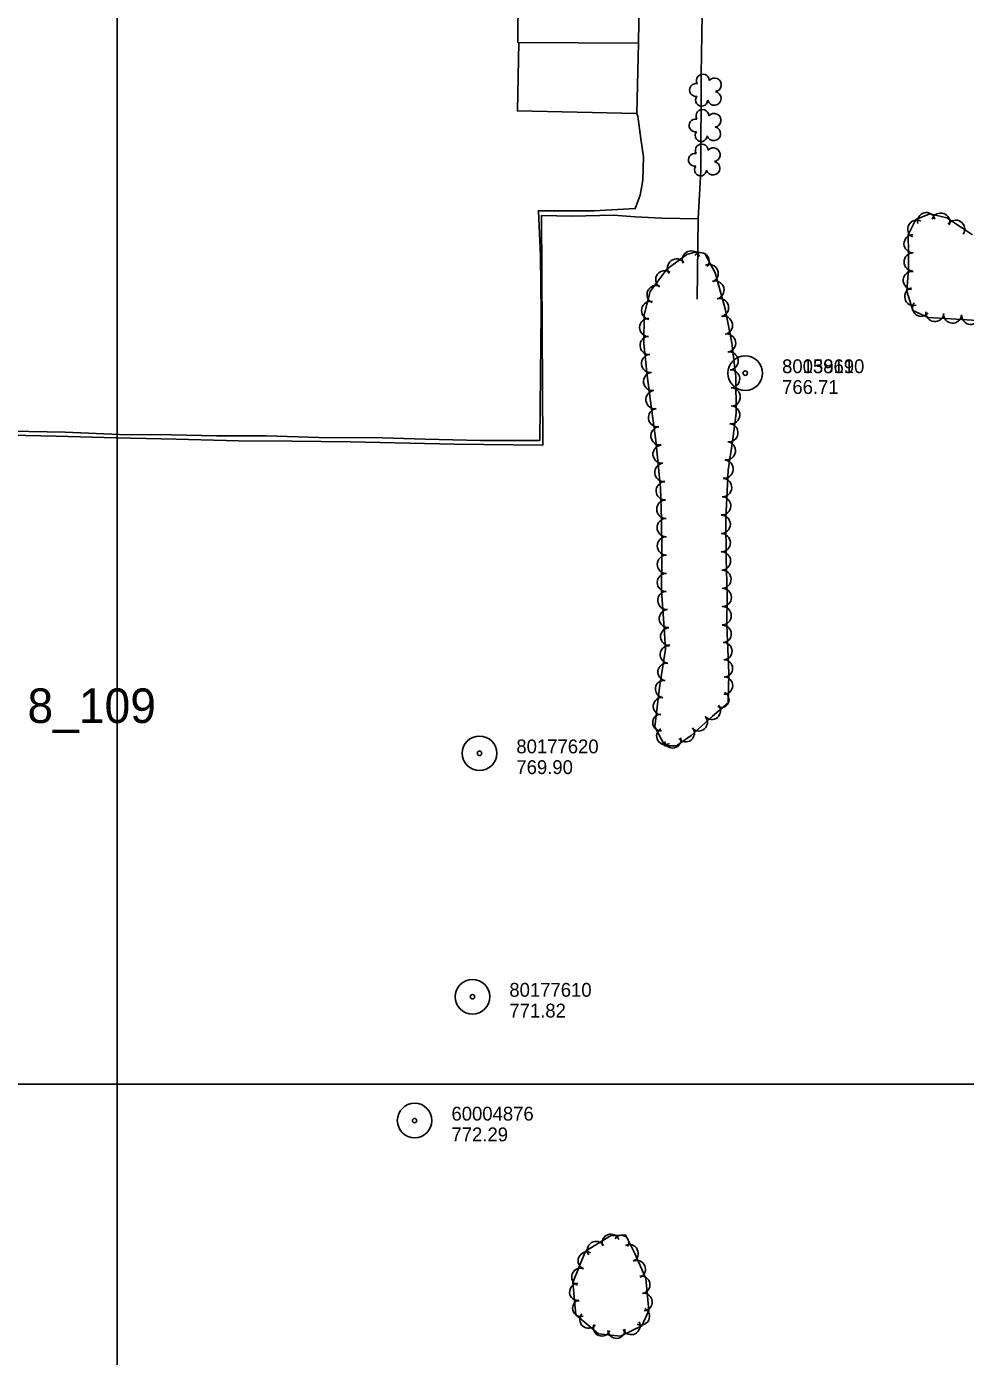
# Model space of a CAD drawing. Extents: x 591954 to 597000, y 198576 to 213500.
# Drawn here: x 594461 to 594868, y 203882 to 204459 of the extents above; entities that cross this region are included whole.
import ezdxf

# ---------------------------------------------------------------- set-up
doc = ezdxf.new("R2010")
doc.units = 0
for name, color, linetype in [('Level 10', 7, 'Continuous'), ('Level 12', 7, 'Continuous'), ('Level 15', 7, 'Continuous'), ('Level 17', 7, 'Continuous'), ('Level 18', 7, 'Continuous'), ('Level 4', 7, 'Continuous'), ('Level 6', 7, 'Continuous')]:
    doc.layers.add(name, color=color, linetype=linetype)

msp = doc.modelspace()

# ---------------------------------------------------------------- linework, layer by layer
at = {"layer": 'Level 10'}
for p, q in [((594500, 204000), (594500, 205500)), ((594500, 203000), (594500, 204500)), ((593000, 204000), (595500, 204000)), ((593500, 204000), (595500, 204000))]:
    msp.add_line(p, q, dxfattribs=at)
at = {"layer": 'Level 12'}
msp.add_lwpolyline([(594674.68, 204574.47), (594673.92, 204451.9), (594726.25, 204451.57), (594728.14, 204573.62), (594674.68, 204574.47)], dxfattribs=at)
at = {"layer": 'Level 15'}
for points in [[(594754.08, 204472.87), (594753.51, 204438.08), (594753.28, 204396.43), (594752.17, 204375.34)], [(594752.17, 204375.34), (594736.43, 204375.71), (594724.75, 204376.29), (594715.46, 204377), (594697.51, 204376.56), (594684.17, 204376.79), (594684.8, 204277.26), (594646.2, 204277.59), (594601.26, 204278.64), (594576, 204279.01), (594552.68, 204279.16), (594525.61, 204279.87), (594499.47, 204280.41), (594473.45, 204281.09), (594446.78, 204281.74), (594435.38, 204281.84), (594425.62, 204279.31), (594415.91, 204281.81)], [(594752.17, 204375.34), (594751.77, 204340.63)]]:
    msp.add_lwpolyline(points, dxfattribs=at)
at = {"layer": 'Level 17'}
for points in [[(594725.58, 204421.13), (594673.67, 204422.2), (594674.28, 204451.9)], [(594726.21, 204451.57), (594725.58, 204421.13)], [(594725.58, 204421.13), (594725.93, 204419.94), (594727.25, 204410.16), (594728.39, 204402.27), (594728.18, 204392.16), (594726.96, 204385.66), (594724.87, 204379.87), (594706.82, 204378.94), (594682.82, 204378.9), (594683.75, 204359.27), (594683.97, 204334.47), (594683.77, 204307.86), (594683.38, 204279.19), (594657.72, 204279.26), (594633.71, 204279.8), (594615.08, 204280.37), (594587.5, 204280.59), (594564.63, 204281.21), (594543.07, 204281.25), (594523.57, 204281.66), (594500.96, 204281.92), (594477.34, 204282.87), (594453.76, 204283.23)]]:
    msp.add_lwpolyline(points, dxfattribs=at)
at = {"layer": 'Level 18'}
for points in [[(594871.24, 204368.51), (594866.87, 204371.41), (594860.14, 204375.87), (594852.65, 204377.58), (594846.61, 204375.17), (594843.33, 204368.53), (594843.42, 204360.93), (594843.46, 204353.69), (594842.67, 204344.08), (594845.29, 204335.65), (594851.92, 204332.57), (594862.02, 204332.06), (594875.71, 204331.1)], [(594764.6, 204199.17), (594764.77, 204212.46), (594764.29, 204228.02), (594764.17, 204245.43), (594765.23, 204266.33), (594767.08, 204278.8), (594768.64, 204291.15), (594768.45, 204306.94), (594766.72, 204321.68), (594763.82, 204336.38), (594759.51, 204351.95), (594755.03, 204360.39), (594751.29, 204361.06), (594747.27, 204359.89), (594738.5, 204353.62), (594731.39, 204343.89), (594728.69, 204333.74), (594728.56, 204321.28), (594729.95, 204307.46), (594731.71, 204294.15), (594733.82, 204279.3), (594735.84, 204258.75), (594736.18, 204245.1), (594736.35, 204230.87), (594736.21, 204214.02), (594737.41, 204197.95)], [(594737.41, 204197.95), (594737.92, 204188.71), (594735.44, 204172.05), (594733.33, 204155.01), (594737.68, 204146.84), (594742.73, 204146.74), (594749.05, 204151.28), (594758.35, 204159.72), (594765.18, 204165.45), (594765.47, 204178.29), (594764.6, 204199.17)], [(594730.72, 203901.8), (594729.38, 203915.75), (594724.71, 203926.56), (594720.55, 203934.66), (594714.04, 203934.2), (594703.29, 203927.56), (594697.82, 203913.93), (594699.08, 203899.94), (594708.95, 203891.7), (594718.38, 203890.77), (594727.77, 203895.21), (594730.72, 203901.8)]]:
    msp.add_lwpolyline(points, dxfattribs=at)
for centre, radius, start, end in [((594754.21, 204435.37), 2.78, 1.39455, 209.16754), ((594759.25, 204433.52), 2.97, 278.42366, 139.65754), ((594751.21, 204431.3), 2.78, 78.07156, 279.08261), ((594759.14, 204427.66), 2.97, 196.07448, 79.04774), ((594753.67, 204426.9), 2.61, 140.77971, 358.71232), ((594751, 204415.93), 2.78, 78.07156, 279.08261), ((594754, 204420.01), 2.78, 1.39455, 209.16754), ((594759.04, 204418.15), 2.97, 278.42366, 139.65754), ((594753.46, 204411.53), 2.61, 140.77971, 358.71232), ((594758.93, 204412.29), 2.97, 196.07448, 79.04774), ((594753.7, 204405.09), 2.78, 1.39455, 209.16754), ((594758.74, 204403.24), 2.97, 278.42366, 139.65754), ((594750.7, 204401.02), 2.78, 78.07156, 279.08261), ((594758.63, 204397.38), 2.97, 196.07448, 79.04774), ((594753.16, 204396.62), 2.61, 140.77971, 358.71232), ((594851.19, 204374.32), 3.81, 14.08767, 194.07234), ((594857.46, 204374.05), 3.89, 341.97598, 161.96066), ((594846.96, 204370.95), 3.88, 61.74191, 241.72659), ((594863.93, 204370.89), 3.94, 326.4448, 146.42948), ((594845.44, 204364.58), 3.94, 90.6411, 270.62578), ((594749.1, 204357.64), 3.86, 21.67135, 201.65603), ((594753.36, 204357.15), 3.59, 318.02994, 138.01462), ((594845.46, 204356.69), 3.93, 89.76001, 269.74469), ((594742.79, 204354.08), 3.96, 36.09353, 216.07821), ((594756.92, 204351.71), 3.94, 292.96781, 112.95248), ((594737.7, 204349), 3.97, 53.84544, 233.83012), ((594759.41, 204344.51), 3.97, 285.46607, 105.45074), ((594845.11, 204348.67), 3.93, 85.29119, 265.27586), ((594733.86, 204342.62), 3.9, 64.71425, 244.69893), ((594845.72, 204341.67), 3.91, 104.95797, 284.94265), ((594731.53, 204335.67), 3.95, 77.76138, 257.74606), ((594761.41, 204336.89), 3.96, 283.91069, 103.89537), ((594848.89, 204336.81), 3.7, 144.6896, 324.67428), ((594730.71, 204328.26), 3.97, 89.42266, 269.40734), ((594763.11, 204329.24), 3.97, 281.19864, 101.18332), ((594854.89, 204334.69), 3.9, 173.70726, 353.69194), ((594862.59, 204334.05), 3.93, 176.49582, 356.4805), ((594870.46, 204333.53), 3.94, 175.97081, 355.95548), ((594764.49, 204321.52), 3.96, 279.04341, 99.02809), ((594730.89, 204320.48), 3.96, 93.32869, 273.31336), ((594731.52, 204312.67), 3.97, 95.75131, 275.73599), ((594765.56, 204313.74), 3.97, 276.6732, 96.65788), ((594732.41, 204304.84), 3.97, 97.27779, 277.26247), ((594766.22, 204305.98), 3.96, 273.06757, 93.05225), ((594733.43, 204296.99), 3.97, 97.6128, 277.59748), ((594766.48, 204298.14), 3.97, 270.72265, 90.70733), ((594734.52, 204289.15), 3.97, 98.1153, 278.09998), ((594766.25, 204290.4), 3.96, 265.84264, 85.82732), ((594735.59, 204281.26), 3.97, 97.40233, 277.387), ((594765.47, 204282.63), 3.97, 262.75186, 82.73654), ((594736.5, 204273.31), 3.97, 95.61334, 275.59802), ((594764.39, 204274.81), 3.97, 261.57937, 81.56405), ((594737.27, 204265.42), 3.97, 95.60545, 275.59013), ((594763.39, 204266.86), 3.96, 264.0978, 84.08248), ((594762.77, 204258.85), 3.97, 267.08142, 87.0661), ((594737.85, 204257.41), 3.97, 92.76903, 272.75371), ((594738.15, 204249.43), 3.97, 91.43037, 271.41505), ((594762.37, 204250.92), 3.97, 267.08179, 87.06647), ((594738.3, 204241.47), 3.97, 90.73709, 270.72177), ((594762.15, 204242.9), 3.97, 269.81985, 89.80453), ((594762.17, 204234.94), 3.97, 270.4265, 90.41118), ((594738.38, 204233.53), 3.97, 90.51316, 270.49783), ((594738.38, 204225.56), 3.97, 89.52383, 269.50851), ((594762.28, 204226.98), 3.97, 271.26432, 91.249), ((594738.33, 204217.64), 3.97, 89.73321, 269.71789), ((594762.49, 204219.03), 3.97, 271.75539, 91.74007), ((594738.6, 204209.88), 3.97, 94.28673, 274.27141), ((594762.62, 204211.16), 3.97, 270.10156, 90.08624), ((594739.17, 204202.01), 3.92, 94.28425, 274.26893), ((594762.57, 204203.25), 3.97, 269.26388, 89.24856), ((594762.8, 204195.37), 3.73, 272.41537, 92.40005), ((594739.59, 204194.21), 3.77, 93.14953, 273.13421), ((594739.39, 204186.4), 3.76, 84.03819, 264.02287), ((594763.1, 204187.88), 3.77, 272.41861, 92.40329), ((594738.45, 204178.85), 3.77, 81.55284, 261.53751), ((594763.36, 204180.38), 3.77, 271.62034, 91.60502), ((594763.38, 204172.95), 3.77, 268.70744, 88.69211), ((594737.39, 204171.42), 3.77, 82.31955, 262.30423), ((594762.14, 204166.85), 3.43, 243.80089, 63.78557), ((594736.43, 204163.96), 3.77, 82.95714, 262.94182), ((594758.09, 204162.01), 3.77, 220.73433, 40.719), ((594736.05, 204156.91), 3.63, 92.22573, 272.21041), ((594752.41, 204156.99), 3.77, 222.22151, 42.20619), ((594737.81, 204150.99), 3.69, 120.18024, 300.16492), ((594746.77, 204152.24), 3.76, 217.90401, 37.88869), ((594741.1, 204149.44), 3.59, 192.37624, 12.36092), ((594714.24, 203931.25), 3.73, 21.01594, 201.00062), ((594718.83, 203931.28), 3.21, 327.71054, 147.69522), ((594703.87, 203923.42), 3.81, 66.87919, 246.86387), ((594707.85, 203928.01), 3.84, 31.72087, 211.70554), ((594722.3, 203926.66), 3.83, 295.8675, 115.85217), ((594725.46, 203919.77), 3.84, 293.34063, 113.32531), ((594701.07, 203916.43), 3.82, 69.43053, 249.4152), ((594727.43, 203912.98), 3.81, 278.75382, 98.7385), ((594700.2, 203909.92), 3.84, 95.14596, 275.13064), ((594701.3, 203902.87), 3.64, 104.48115, 284.46583), ((594728.35, 203905.51), 3.84, 275.51386, 95.49853), ((594704.59, 203897.95), 3.84, 140.15905, 320.14373), ((594727.32, 203899.28), 3.75, 244.06091, 64.04559), ((594710.36, 203894.41), 3.67, 158.73288, 338.71756), ((594716.67, 203893.48), 3.72, 183.71666, 3.70134), ((594723.12, 203895.23), 3.84, 205.29308, 25.27776)]:
    msp.add_arc(centre, radius, start, end, dxfattribs=at)
at = {"layer": 'Level 6'}
for centre, radius in [((594772.59, 204308.46), 7.5), ((594772.59, 204308.46), 7.5), ((594772.59, 204308.46), 7.5), ((594772.59, 204308.46), 7.5), ((594772.59, 204308.46), 0.96), ((594772.59, 204308.46), 0.96), ((594772.59, 204308.46), 0.96), ((594772.59, 204308.46), 0.96), ((594657.25, 204143.55), 7.5), ((594657.25, 204143.55), 7.5), ((594657.25, 204143.55), 0.96), ((594657.25, 204143.55), 0.96), ((594654.2, 204037.95), 7.5), ((594654.2, 204037.95), 7.5), ((594654.2, 204037.95), 0.96), ((594654.2, 204037.95), 0.96), ((594629.08, 203984.24), 7.5), ((594629.08, 203984.24), 7.5), ((594629.08, 203984.24), 0.96), ((594629.08, 203984.24), 0.96)]:
    msp.add_circle(centre, radius, dxfattribs=at)

# ---------------------------------------------------------------- texts
at = {"layer": 'Level 4'}
msp.add_text('8_109', height=15, dxfattribs=at).set_placement((594461.04, 204156.7))
msp.add_text('8_109', height=15, dxfattribs=at).set_placement((594461.04, 204156.7))
at = {"layer": 'Level 6'}
for s, p in [('30058190', (594788.59, 204308.46)), ('30058190', (594788.59, 204308.46)), ('80139610', (594788.59, 204308.46)), ('80139610', (594788.59, 204308.46)), ('766.71', (594788.59, 204299.46)), ('766.71', (594788.59, 204299.46)), ('766.71', (594788.59, 204299.46)), ('766.71', (594788.59, 204299.46)), ('80177620', (594673.25, 204143.55)), ('80177620', (594673.25, 204143.55)), ('769.90', (594673.25, 204134.55)), ('769.90', (594673.25, 204134.55)), ('80177610', (594670.2, 204037.95)), ('80177610', (594670.2, 204037.95)), ('771.82', (594670.2, 204028.95)), ('771.82', (594670.2, 204028.95)), ('60004876', (594645.08, 203984.24)), ('60004876', (594645.08, 203984.24)), ('772.29', (594645.08, 203975.24)), ('772.29', (594645.08, 203975.24))]:
    msp.add_text(s, height=6, dxfattribs=at).set_placement(p)

doc.saveas('drawing.dxf')
